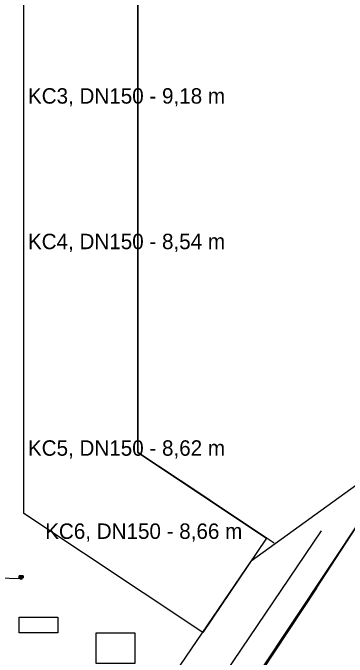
# Model space of a CAD drawing. Extents: x -264031 to -263588, y -1242281 to -1242059.
# Drawn here: x -263782.8 to -263739.4, y -1242227.5 to -1242144 of the extents above; entities that cross this region are included whole.
import ezdxf

# ---------------------------------------------------------------- set-up
doc = ezdxf.new("R2010")
doc.units = 0
doc.layers.add('KFA_2D_SITUACIA_DSP', color=7, linetype='Continuous')
doc.layers.add('POPIS', color=7, linetype='Continuous')

msp = doc.modelspace()

# ---------------------------------------------------------------- linework, layer by layer
at = {"layer": 'KFA_2D_SITUACIA_DSP'}
for p, q in [((-263766.58, -1242144.85), (-263766.58, -1242074.389)), ((-263766.58, -1242201.01), (-263766.58, -1242144.85)), ((-263758.42, -1242206.43), (-263766.58, -1242201.01)), ((-263736.134, -1242203.7), (-263751.891, -1242215.1)), ((-263785.333, -1242281.427), (-263734.49, -1242204.937)), ((-263757.19, -1242207.25), (-263758.42, -1242206.43)), ((-263748.89, -1242212.77), (-263757.19, -1242207.25)), ((-263790.417, -1242281.427), (-263742.736, -1242211.145)), ((-263797.061, -1242281.427), (-263751.864, -1242215.081)), ((-263751.891, -1242215.1), (-263751.891, -1242215.1)), ((-263781.968, -1242216.987), (-263781.468, -1242216.987)), ((-263781.968, -1242217.277), (-263781.968, -1242216.987)), ((-263781.968, -1242216.987), (-263781.468, -1242217.277)), ((-263781.968, -1242216.987), (-263781.468, -1242217.277)), ((-263781.468, -1242216.987), (-263781.968, -1242216.987)), ((-263781.468, -1242216.987), (-263781.468, -1242217.277)), ((-263781.468, -1242217.277), (-263781.468, -1242216.987)), ((-263781.818, -1242217.375), (-263790.409, -1242217.218)), ((-263781.468, -1242217.277), (-263781.968, -1242217.277)), ((-263743.421, -1242218.608), (-263752.521, -1242232.37))]:
    msp.add_line(p, q, dxfattribs=at)
for points in [[(-263766.58, -1242083.485), (-263766.58, -1242201.01), (-263749.879, -1242212.113), (-263758.153, -1242224.365), (-263781.364, -1242208.936), (-263781.371, -1242084.903)], [(-263781.968, -1242222.382), (-263776.968, -1242222.382), (-263776.968, -1242224.382), (-263781.968, -1242224.382)], [(-263771.968, -1242224.382), (-263766.968, -1242224.382), (-263766.968, -1242228.382), (-263771.968, -1242228.382)]]:
    msp.add_lwpolyline(points, close=True, dxfattribs=at)
msp.add_lwpolyline([(-263743.421, -1242218.608), (-263734.49, -1242204.937), (-263734.475, -1242204.91), (-263734.475, -1242204.91)], dxfattribs=at)
msp.add_circle((-263781.718, -1242217.377), 0.1, dxfattribs=at)

# ---------------------------------------------------------------- texts
at = {"layer": 'POPIS'}
for s, p in [('KC3, DN150 - 9,18 m', (-263780.834, -1242155.753)), ('KC4, DN150 - 8,54 m', (-263780.834, -1242174.631)), ('KC5, DN150 - 8,62 m', (-263780.834, -1242201.424)), ('KC6, DN150 - 8,66 m', (-263778.599, -1242212.208))]:
    msp.add_text(s, height=2, dxfattribs=at).set_placement(p)

doc.saveas('drawing.dxf')
